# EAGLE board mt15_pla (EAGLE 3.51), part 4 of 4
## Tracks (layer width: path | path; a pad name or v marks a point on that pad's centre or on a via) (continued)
N$297  (via drill 0.61 pad 1.02)
  Top 0.305: 103.81,47.88 103.81,48.25 v104.14,48.58
  Bottom 0.305: J285. 103.82,48.26 v104.14,48.58
N$298  (via drill 0.61 pad 1.02)
  Top 0.406: 3.5,53.72 3.5,53.67 v3.17,53.34
  Bottom 0.406: J287. 3.49,53.66 v3.17,53.34
N$299  (via drill 0.61 pad 1.02)
  Top 0.406: 7.32,53.72 7.32,53.67 v6.99,53.34
  Bottom 0.406: J288. 7.3,53.66 v6.99,53.34
N$300  (via drill 0.61 pad 1.02)
  Top 0.406: 11.12,53.72 11.12,53.67 v10.79,53.34
  Bottom 0.406: J289. 11.11,53.66 v10.79,53.34
N$301  (via drill 0.61 pad 1.02)
  Top 0.305: 110.11,53.34 109.16,54.29 107.63,54.29 | 73.34,54.29 77.15,54.29 | 77.15,54.29 80.96,54.29 | 80.96,54.29 84.77,54.29 | 84.77,54.29 88.58,54.29 | 88.58,54.29 92.39,54.29 | 92.39,54.29 96.2,54.29 | 96.2,54.29 100.01,54.29 | 100.01,54.29 103.82,54.29 | 103.82,54.29 107.63,54.29 | v70.17,54.29 73.34,54.29 | 107.67,53.09 107.63,53.09 107.63,54.29 | 103.86,53.09 103.82,53.09 103.82,54.29 | 96.24,53.09 96.2,53.09 96.2,54.29 | 100.05,53.09 100.01,53.09 100.01,54.29 | 73.38,53.09 73.34,53.09 73.34,54.29 | 77.19,53.09 77.15,53.09 77.15,54.29 | 81,53.09 80.96,53.09 80.96,54.29 | 84.81,53.09 84.77,53.09 84.77,54.29 | 88.62,53.09 88.58,53.09 88.58,54.29 | 92.43,53.09 92.39,53.09 92.39,54.29
  Bottom 0.305: 5.21,53.66 5.08,53.66 5.08,52.07 8.89,52.07 | 8.89,52.07 12.7,52.07 | 12.7,52.07 16.51,52.07 | 16.51,52.07 20.32,52.07 | 20.32,52.07 24.13,52.07 | 24.13,52.07 27.94,52.07 | 27.94,52.07 31.75,52.07 | 31.75,52.07 35.56,52.07 | 35.56,52.07 39.37,52.07 | 39.37,52.07 43.18,52.07 | 43.18,52.07 46.99,52.07 | 46.99,52.07 50.8,52.07 | 50.8,52.07 54.61,52.07 | 54.61,52.07 58.42,52.07 | 58.42,52.07 62.23,52.07 | 62.36,53.66 62.23,53.66 62.23,52.07 | 58.55,53.66 58.42,53.66 58.42,52.07 | 54.74,53.66 54.61,53.66 54.61,52.07 | 50.93,53.66 50.8,53.66 50.8,52.07 | 47.12,53.66 46.99,53.66 46.99,52.07 | 39.5,53.66 39.37,53.66 39.37,52.07 | 43.31,53.66 43.18,53.66 43.18,52.07 | 24.26,53.66 24.13,53.66 24.13,52.07 | 20.45,53.66 20.32,53.66 20.32,52.07 | 28.07,53.66 27.94,53.66 27.94,52.07 | 31.88,53.66 31.75,53.66 31.75,52.07 | 35.69,53.66 35.56,53.66 35.56,52.07 | 9.02,53.66 8.89,53.66 8.89,52.07 | 12.83,53.66 12.7,53.66 12.7,52.07 | 16.64,53.66 16.51,53.66 16.51,52.07 | 62.23,52.07 67.94,52.07 v70.17,54.29
N$302  (via drill 0.61 pad 1.02)
  Top 0.406: 60.66,53.72 60.66,53.67 v60.33,53.34
  Bottom 0.406: J302. 60.64,53.66 v60.33,53.34
N$303  (via drill 0.61 pad 1.02)
  Top 0.406: 56.84,53.72 56.84,53.67 v56.52,53.34
  Bottom 0.406: J301. 56.83,53.66 v56.52,53.34
N$304  (via drill 0.61 pad 1.02)
  Top 0.406: 53.03,53.72 53.03,53.67 v52.7,53.34
  Bottom 0.406: J300. 53.02,53.66 v52.7,53.34
N$305  (via drill 0.61 pad 1.02)
  Top 0.406: 49.23,53.72 49.23,53.67 v48.9,53.34
  Bottom 0.406: J299. 49.21,53.66 v48.9,53.34
N$306  (via drill 0.61 pad 1.02)
  Top 0.406: 45.41,53.72 45.41,53.67 v45.09,53.34
  Bottom 0.406: J298. 45.4,53.66 v45.09,53.34
N$307  (via drill 0.61 pad 1.02)
  Top 0.406: 22.55,53.72 22.55,53.67 v22.23,53.34
  Bottom 0.406: J292. 22.54,53.66 v22.23,53.34
N$308  (via drill 0.61 pad 1.02)
  Top 0.406: 18.75,53.72 18.75,53.67 v18.41,53.34
  Bottom 0.406: J291. 18.73,53.66 v18.41,53.34
N$309  (via drill 0.61 pad 1.02)
  Top 0.406: 14.94,53.72 14.94,53.67 v14.61,53.34
  Bottom 0.406: J290. 14.92,53.66 v14.61,53.34
N$310  (via drill 0.61 pad 1.02)
  Top 0.406: 26.36,53.72 26.36,53.67 v26.04,53.34
  Bottom 0.406: J293. 26.35,53.66 v26.04,53.34
N$311  (via drill 0.61 pad 1.02)
  Top 0.406: 30.18,53.72 30.18,53.67 v29.84,53.34
  Bottom 0.406: J294. 30.16,53.66 v29.84,53.34
N$312  (via drill 0.61 pad 1.02)
  Top 0.406: 33.98,53.72 33.98,53.67 v33.66,53.34
  Bottom 0.406: J295. 33.97,53.66 v33.66,53.34
N$313  (via drill 0.61 pad 1.02)
  Top 0.406: 37.8,53.72 37.8,53.67 v37.47,53.34
  Bottom 0.406: J296. 37.78,53.66 v37.47,53.34
N$314  (via drill 0.61 pad 1.02)
  Top 0.406: 41.6,53.72 41.6,53.67 v41.27,53.34
  Bottom 0.406: J297. 41.59,53.66 v41.27,53.34
N$315  (via drill 0.61 pad 1.02)
  Top 0.305: 105.74,53.09 105.74,52.72 v105.41,52.39
  Bottom 0.305: J312. 105.73,52.7 v105.41,52.39
N$316  (via drill 0.61 pad 1.02)
  Top 0.305: 71.45,53.09 71.45,52.72 v71.12,52.39
  Bottom 0.305: J303. 71.44,52.7 v71.12,52.39
N$317  (via drill 0.61 pad 1.02)
  Top 0.305: 75.26,53.09 75.26,52.72 v74.93,52.39
  Bottom 0.305: J304. 75.25,52.7 v74.93,52.39
N$318  (via drill 0.61 pad 1.02)
  Top 0.305: 79.07,53.09 79.07,52.72 v78.74,52.39
  Bottom 0.305: J305. 79.06,52.7 v78.74,52.39
N$319  (via drill 0.61 pad 1.02)
  Top 0.305: 82.88,53.09 82.88,52.72 v82.55,52.39
  Bottom 0.305: J306. 82.87,52.7 v82.55,52.39
N$320  (via drill 0.61 pad 1.02)
  Top 0.305: 86.69,53.09 86.69,52.72 v86.36,52.39
  Bottom 0.305: J307. 86.68,52.7 v86.36,52.39
N$321  (via drill 0.61 pad 1.02)
  Top 0.305: 90.5,53.09 90.5,52.72 v90.17,52.39
  Bottom 0.305: J308. 90.49,52.7 v90.17,52.39
N$322  (via drill 0.61 pad 1.02)
  Top 0.305: 94.31,53.09 94.31,52.72 v93.98,52.39
  Bottom 0.305: J309. 94.3,52.7 v93.98,52.39
N$323  (via drill 0.61 pad 1.02)
  Top 0.305: 98.12,53.09 98.12,52.72 v97.79,52.39
  Bottom 0.305: J310. 98.11,52.7 v97.79,52.39
N$324  (via drill 0.61 pad 1.02)
  Top 0.305: 101.93,53.09 101.93,52.72 v101.6,52.39
  Bottom 0.305: J311. 101.92,52.7 v101.6,52.39
N$325  (via drill 0.61 pad 1.02)
  Top 0.406: 7.92,56.13 7.92,56.19 v8.26,56.52
  Bottom 0.406: J313. 7.94,56.2 v8.26,56.52
N$326  (via drill 0.61 pad 1.02)
  Top 0.406: 11.73,56.13 11.73,56.19 v12.06,56.52
  Bottom 0.406: J314. 11.75,56.2 v12.06,56.52
N$327  (via drill 0.61 pad 1.02)
  Top 0.406: 15.54,56.13 15.54,56.19 v15.88,56.52
  Bottom 0.406: J315. 15.56,56.2 v15.88,56.52
N$328  (via drill 0.61 pad 1.02)
  Top 0.305: 110.11,55.88 109.16,54.93 105.73,54.93 | 71.44,54.93 71.12,54.93 v70.17,55.88 | 71.44,54.93 75.25,54.93 | 75.25,54.93 79.06,54.93 | 79.06,54.93 82.87,54.93 | 82.87,54.93 86.68,54.93 | 86.68,54.93 90.49,54.93 | 90.49,54.93 94.3,54.93 | 94.3,54.93 98.11,54.93 | 98.11,54.93 101.92,54.93 | 101.92,54.93 105.73,54.93 | 98.07,56.13 98.11,56.13 98.11,54.93 | 101.88,56.13 101.92,56.13 101.92,54.93 | 105.69,56.13 105.73,56.13 105.73,54.93 | 82.83,56.13 82.87,56.13 82.87,54.93 | 86.64,56.13 86.68,56.13 86.68,54.93 | 90.45,56.13 90.49,56.13 90.49,54.93 | 94.26,56.13 94.3,56.13 94.3,54.93 | 71.4,56.13 71.44,56.13 71.44,54.93 | 75.21,56.13 75.25,56.13 75.25,54.93 | 79.02,56.13 79.06,56.13 79.06,54.93
  Bottom 0.305: 6.22,56.2 6.35,56.2 6.35,57.78 10.16,57.78 | 10.16,57.78 13.97,57.78 | 13.97,57.78 17.78,57.78 | 17.78,57.78 21.59,57.78 | 21.59,57.78 25.4,57.78 | 25.4,57.78 29.21,57.78 | 29.21,57.78 33.02,57.78 | 33.02,57.78 36.83,57.78 | 36.83,57.78 40.64,57.78 | 40.64,57.78 44.45,57.78 | 44.45,57.78 48.26,57.78 | 48.26,57.78 52.07,57.78 | 52.07,57.78 55.88,57.78 | 55.88,57.78 59.69,57.78 | 59.69,57.78 63.5,57.78 | 40.51,56.2 40.64,56.2 40.64,57.78 | 44.32,56.2 44.45,56.2 44.45,57.78 | 48.13,56.2 48.26,56.2 48.26,57.78 | 51.94,56.2 52.07,56.2 52.07,57.78 | 55.75,56.2 55.88,56.2 55.88,57.78 | 59.56,56.2 59.69,56.2 59.69,57.78 | 63.37,56.2 63.5,56.2 63.5,57.78 | 36.7,56.2 36.83,56.2 36.83,57.78 | 32.89,56.2 33.02,56.2 33.02,57.78 | 29.08,56.2 29.21,56.2 29.21,57.78 | 25.27,56.2 25.4,56.2 25.4,57.78 | 21.46,56.2 21.59,56.2 21.59,57.78 | 13.84,56.2 13.97,56.2 13.97,57.78 | 17.65,56.2 17.78,56.2 17.78,57.78 | 10.03,56.2 10.16,56.2 10.16,57.78 | 63.5,57.78 68.26,57.78 v70.17,55.88
N$329  (via drill 0.61 pad 1.02)
  Top 0.406: 65.08,56.13 65.08,56.19 v65.41,56.52
  Bottom 0.406: J328. 65.09,56.2 v65.41,56.52
N$330  (via drill 0.61 pad 1.02)
  Top 0.406: 61.27,56.13 61.27,56.19 v61.59,56.52
  Bottom 0.406: J327. 61.28,56.2 v61.59,56.52
N$331  (via drill 0.61 pad 1.02)
  Top 0.406: 57.45,56.13 57.45,56.19 v57.78,56.52
  Bottom 0.406: J326. 57.47,56.2 v57.78,56.52
N$332  (via drill 0.61 pad 1.02)
  Top 0.406: 53.65,56.13 53.65,56.19 v53.98,56.52
  Bottom 0.406: J325. 53.66,56.2 v53.98,56.52
N$333  (via drill 0.61 pad 1.02)
  Top 0.406: 49.84,56.13 49.84,56.19 v50.16,56.52
  Bottom 0.406: J324. 49.85,56.2 v50.16,56.52
N$334  (via drill 0.61 pad 1.02)
  Top 0.406: 26.98,56.13 26.98,56.19 v27.3,56.52
  Bottom 0.406: J318. 26.99,56.2 v27.3,56.52
N$335  (via drill 0.61 pad 1.02)
  Top 0.406: 23.16,56.13 23.16,56.19 v23.5,56.52
  Bottom 0.406: J317. 23.18,56.2 v23.5,56.52
N$336  (via drill 0.61 pad 1.02)
  Top 0.406: 19.36,56.13 19.36,56.19 v19.68,56.52
  Bottom 0.406: J316. 19.37,56.2 v19.68,56.52
N$337  (via drill 0.61 pad 1.02)
  Top 0.406: 30.79,56.13 30.79,56.19 v31.11,56.52
  Bottom 0.406: J319. 30.8,56.2 v31.11,56.52
N$338  (via drill 0.61 pad 1.02)
  Top 0.406: 34.59,56.13 34.59,56.19 v34.92,56.52
  Bottom 0.406: J320. 34.61,56.2 v34.92,56.52
N$339  (via drill 0.61 pad 1.02)
  Top 0.406: 38.41,56.13 38.41,56.19 v38.73,56.52
  Bottom 0.406: J321. 38.42,56.2 v38.73,56.52
N$340  (via drill 0.61 pad 1.02)
  Top 0.406: 42.22,56.13 42.22,56.19 v42.55,56.52
  Bottom 0.406: J322. 42.23,56.2 v42.55,56.52
N$341  (via drill 0.61 pad 1.02)
  Top 0.406: 46.02,56.13 46.02,56.19 v46.35,56.52
  Bottom 0.406: J323. 46.04,56.2 v46.35,56.52
N$342  (via drill 0.61 pad 1.02)
  Top 0.305: 107.62,56.13 107.62,56.5 v107.95,56.83
  Bottom 0.305: J338. 107.63,56.2 107.63,56.52 v107.95,56.83
N$343  (via drill 0.61 pad 1.02)
  Top 0.305: 73.33,56.13 73.33,56.5 v73.66,56.83
  Bottom 0.305: J329. 73.34,56.52 v73.66,56.83
N$344  (via drill 0.61 pad 1.02)
  Top 0.305: 77.14,56.13 77.14,56.5 v77.47,56.83
  Bottom 0.305: J330. 77.15,56.52 v77.47,56.83
N$345  (via drill 0.61 pad 1.02)
  Top 0.305: 80.95,56.13 80.95,56.5 v81.28,56.83
  Bottom 0.305: J331. 80.96,56.52 v81.28,56.83
N$346  (via drill 0.61 pad 1.02)
  Top 0.305: 84.76,56.13 84.76,56.5 v85.09,56.83
  Bottom 0.305: J332. 84.77,56.52 v85.09,56.83
N$347  (via drill 0.61 pad 1.02)
  Top 0.305: 88.57,56.13 88.57,56.5 v88.9,56.83
  Bottom 0.305: J333. 88.58,56.52 v88.9,56.83
N$348  (via drill 0.61 pad 1.02)
  Top 0.305: 92.38,56.13 92.38,56.5 v92.71,56.83
  Bottom 0.305: J334. 92.39,56.52 v92.71,56.83
N$349  (via drill 0.61 pad 1.02)
  Top 0.305: 96.19,56.13 96.19,56.5 v96.52,56.83
  Bottom 0.305: J335. 96.2,56.52 v96.52,56.83
N$350  (via drill 0.61 pad 1.02)
  Top 0.305: 100,56.13 100,56.5 v100.33,56.83
  Bottom 0.305: J336. 100.01,56.52 v100.33,56.83
N$351  (via drill 0.61 pad 1.02)
  Top 0.305: 103.81,56.13 103.81,56.5 v104.14,56.83
  Bottom 0.305: J337. 103.82,56.52 v104.14,56.83
N$352  (via drill 0.61 pad 1.02)
  Top 0.406: 3.5,61.98 3.5,61.92 v3.17,61.59
  Bottom 0.406: J339. 3.49,61.91 v3.17,61.59
N$353  (via drill 0.61 pad 1.02)
  Top 0.406: 7.32,61.98 7.32,61.92 v6.99,61.59
  Bottom 0.406: J340. 7.3,61.91 v6.99,61.59
N$354  (via drill 0.61 pad 1.02)
  Top 0.406: 11.12,61.98 11.12,61.92 v10.79,61.59
  Bottom 0.406: J341. 11.11,61.91 v10.79,61.59
N$355  (via drill 0.61 pad 1.02)
  Top 0.305: 110.11,61.59 109.16,62.55 107.63,62.55 | 73.34,62.55 77.15,62.55 | 77.15,62.55 80.96,62.55 | 80.96,62.55 84.77,62.55 | 84.77,62.55 88.58,62.55 | 88.58,62.55 92.39,62.55 | 92.39,62.55 96.2,62.55 | 96.2,62.55 100.01,62.55 | 100.01,62.55 103.82,62.55 | 103.82,62.55 107.63,62.55 | v70.17,62.55 73.34,62.55 | 107.67,61.34 107.63,61.34 107.63,62.55 | 103.86,61.34 103.82,61.34 103.82,62.55 | 100.05,61.34 100.01,61.34 100.01,62.55 | 96.24,61.34 96.2,61.34 96.2,62.55 | 92.43,61.34 92.39,61.34 92.39,62.55 | 88.62,61.34 88.58,61.34 88.58,62.55 | 84.81,61.34 84.77,61.34 84.77,62.55 | 73.38,61.34 73.34,61.34 73.34,62.55 | 77.19,61.34 77.15,61.34 77.15,62.55 | 81,61.34 80.96,61.34 80.96,62.55
  Bottom 0.305: 5.21,61.91 5.08,61.91 5.08,60.33 8.89,60.33 | 8.89,60.33 12.7,60.33 | 12.7,60.33 16.51,60.33 | 16.51,60.33 20.32,60.33 | 20.32,60.33 24.13,60.33 | 24.13,60.33 27.94,60.33 | 27.94,60.33 31.75,60.33 | 31.75,60.33 35.56,60.33 | 35.56,60.33 39.37,60.33 | 39.37,60.33 43.18,60.33 | 43.18,60.33 46.99,60.33 | 46.99,60.33 50.8,60.33 | 50.8,60.33 54.61,60.33 | 54.61,60.33 58.42,60.33 | 58.42,60.33 62.23,60.33 | 39.5,61.91 39.37,61.91 39.37,60.33 | 43.31,61.91 43.18,61.91 43.18,60.33 | 47.12,61.91 46.99,61.91 46.99,60.33 | 50.93,61.91 50.8,61.91 50.8,60.33 | 54.74,61.91 54.61,61.91 54.61,60.33 | 58.55,61.91 58.42,61.91 58.42,60.33 | 62.36,61.91 62.23,61.91 62.23,60.33 | 9.02,61.91 8.89,61.91 8.89,60.33 | 12.83,61.91 12.7,61.91 12.7,60.33 | 16.64,61.91 16.51,61.91 16.51,60.33 | 20.45,61.91 20.32,61.91 20.32,60.33 | 24.26,61.91 24.13,61.91 24.13,60.33 | 28.07,61.91 27.94,61.91 27.94,60.33 | 35.69,61.91 35.56,61.91 35.56,60.33 | 31.88,61.91 31.75,61.91 31.75,60.33 | 62.23,60.33 67.94,60.33 v70.17,62.55
N$356  (via drill 0.61 pad 1.02)
  Top 0.406: 60.66,61.98 60.66,61.92 v60.33,61.59
  Bottom 0.406: J354. 60.64,61.91 v60.33,61.59
N$357  (via drill 0.61 pad 1.02)
  Top 0.406: 56.84,61.98 56.84,61.92 v56.52,61.59
  Bottom 0.406: J353. 56.83,61.91 v56.52,61.59
N$358  (via drill 0.61 pad 1.02)
  Top 0.406: 53.03,61.98 53.03,61.92 v52.7,61.59
  Bottom 0.406: J352. 53.02,61.91 v52.7,61.59
N$359  (via drill 0.61 pad 1.02)
  Top 0.406: 49.23,61.98 49.23,61.92 v48.9,61.59
  Bottom 0.406: J351. 49.21,61.91 v48.9,61.59
N$360  (via drill 0.61 pad 1.02)
  Top 0.406: 45.41,61.98 45.41,61.92 v45.09,61.59
  Bottom 0.406: J350. 45.4,61.91 v45.09,61.59
N$361  (via drill 0.61 pad 1.02)
  Top 0.406: 22.55,61.98 22.55,61.92 v22.23,61.59
  Bottom 0.406: J344. 22.54,61.91 v22.23,61.59
N$362  (via drill 0.61 pad 1.02)
  Top 0.406: 18.75,61.98 18.75,61.92 v18.41,61.59
  Bottom 0.406: J343. 18.73,61.91 v18.41,61.59
N$363  (via drill 0.61 pad 1.02)
  Top 0.406: 14.94,61.98 14.94,61.92 v14.61,61.59
  Bottom 0.406: J342. 14.92,61.91 v14.61,61.59
N$364  (via drill 0.61 pad 1.02)
  Top 0.406: 26.36,61.98 26.36,61.92 v26.04,61.59
  Bottom 0.406: J345. 26.35,61.91 v26.04,61.59
N$365  (via drill 0.61 pad 1.02)
  Top 0.406: 30.18,61.98 30.18,61.92 v29.84,61.59
  Bottom 0.406: J346. 30.16,61.91 v29.84,61.59
N$366  (via drill 0.61 pad 1.02)
  Top 0.406: 33.98,61.98 33.98,61.92 v33.66,61.59
  Bottom 0.406: J347. 33.97,61.91 v33.66,61.59
N$367  (via drill 0.61 pad 1.02)
  Top 0.406: 37.8,61.98 37.8,61.92 v37.47,61.59
  Bottom 0.406: J348. 37.78,61.91 v37.47,61.59
N$368  (via drill 0.61 pad 1.02)
  Top 0.406: 41.6,61.98 41.6,61.92 v41.27,61.59
  Bottom 0.406: J349. 41.59,61.91 v41.27,61.59
N$369  (via drill 0.61 pad 1.02)
  Top 0.305: 105.74,61.34 105.74,60.97 v105.41,60.64
  Bottom 0.305: J364. 105.73,60.96 v105.41,60.64
N$370  (via drill 0.61 pad 1.02)
  Top 0.305: 71.45,61.34 71.45,60.97 v71.12,60.64
  Bottom 0.305: J355. 71.44,60.96 v71.12,60.64
N$371  (via drill 0.61 pad 1.02)
  Top 0.305: 75.26,61.34 75.26,60.97 v74.93,60.64
  Bottom 0.305: J356. 75.25,60.96 v74.93,60.64
N$372  (via drill 0.61 pad 1.02)
  Top 0.305: 79.07,61.34 79.07,60.97 v78.74,60.64
  Bottom 0.305: J357. 79.06,60.96 v78.74,60.64
N$373  (via drill 0.61 pad 1.02)
  Top 0.305: 82.88,61.34 82.88,60.97 v82.55,60.64
  Bottom 0.305: J358. 82.87,60.96 v82.55,60.64
N$374  (via drill 0.61 pad 1.02)
  Top 0.305: 86.69,61.34 86.69,60.97 v86.36,60.64
  Bottom 0.305: J359. 86.68,60.96 v86.36,60.64
N$375  (via drill 0.61 pad 1.02)
  Top 0.305: 90.5,61.34 90.5,60.97 v90.17,60.64
  Bottom 0.305: J360. 90.49,60.96 v90.17,60.64
N$376  (via drill 0.61 pad 1.02)
  Top 0.305: 94.31,61.34 94.31,60.97 v93.98,60.64
  Bottom 0.305: J361. 94.3,60.96 v93.98,60.64
N$377  (via drill 0.61 pad 1.02)
  Top 0.305: 98.12,61.34 98.12,60.97 v97.79,60.64
  Bottom 0.305: J362. 98.11,60.96 v97.79,60.64
N$378  (via drill 0.61 pad 1.02)
  Top 0.305: 101.93,61.34 101.93,60.97 v101.6,60.64
  Bottom 0.305: J363. 101.92,60.96 v101.6,60.64
N$379  (via drill 0.61 pad 1.02)
  Top 0.406: 7.92,64.39 7.92,64.44 v8.26,64.77
  Bottom 0.406: J365. 7.94,64.45 v8.26,64.77
N$380  (via drill 0.61 pad 1.02)
  Top 0.406: 11.73,64.39 11.73,64.44 v12.06,64.77
  Bottom 0.406: J366. 11.75,64.45 v12.06,64.77
N$381  (via drill 0.61 pad 1.02)
  Top 0.406: 15.54,64.39 15.54,64.44 v15.88,64.77
  Bottom 0.406: J367. 15.56,64.45 v15.88,64.77
N$382  (via drill 0.61 pad 1.02)
  Top 0.305: 110.11,64.14 109.16,63.18 105.73,63.18 | 71.44,63.18 71.12,63.18 v70.17,64.14 | 71.44,63.18 75.25,63.18 | 75.25,63.18 79.06,63.18 | 79.06,63.18 82.87,63.18 | 82.87,63.18 86.68,63.18 | 86.68,63.18 90.49,63.18 | 90.49,63.18 94.3,63.18 | 94.3,63.18 98.11,63.18 | 98.11,63.18 101.92,63.18 | 101.92,63.18 105.73,63.18 | 98.07,64.39 98.11,64.39 98.11,63.18 | 101.88,64.39 101.92,64.39 101.92,63.18 | 105.69,64.39 105.73,64.39 105.73,63.18 | 82.83,64.39 82.87,64.39 82.87,63.18 | 86.64,64.39 86.68,64.39 86.68,63.18 | 90.45,64.39 90.49,64.39 90.49,63.18 | 94.26,64.39 94.3,64.39 94.3,63.18 | 71.4,64.39 71.44,64.39 71.44,63.18 | 75.21,64.39 75.25,64.39 75.25,63.18 | 79.02,64.39 79.06,64.39 79.06,63.18
  Bottom 0.305: 6.22,64.45 6.35,64.45 6.35,66.04 10.16,66.04 | 10.16,66.04 13.97,66.04 | 13.97,66.04 17.78,66.04 | 17.78,66.04 21.59,66.04 | 21.59,66.04 25.4,66.04 | 25.4,66.04 29.21,66.04 | 29.21,66.04 33.02,66.04 | 33.02,66.04 36.83,66.04 | 36.83,66.04 40.64,66.04 | 40.64,66.04 44.45,66.04 | 44.45,66.04 48.26,66.04 | 48.26,66.04 52.07,66.04 | 52.07,66.04 55.88,66.04 | 55.88,66.04 59.69,66.04 | 59.69,66.04 63.5,66.04 | 63.37,64.45 63.5,64.45 63.5,66.04 | 59.56,64.45 59.69,64.45 59.69,66.04 | 55.75,64.45 55.88,64.45 55.88,66.04 | 51.94,64.45 52.07,64.45 52.07,66.04 | 48.13,64.45 48.26,64.45 48.26,66.04 | 44.32,64.45 44.45,64.45 44.45,66.04 | 40.51,64.45 40.64,64.45 40.64,66.04 | 29.08,64.45 29.21,64.45 29.21,66.04 | 25.27,64.45 25.4,64.45 25.4,66.04 | 21.46,64.45 21.59,64.45 21.59,66.04 | 17.65,64.45 17.78,64.45 17.78,66.04 | 13.84,64.45 13.97,64.45 13.97,66.04 | 10.03,64.45 10.16,64.45 10.16,66.04 | 32.89,64.45 33.02,64.45 33.02,66.04 | 36.7,64.45 36.83,64.45 36.83,66.04 | 63.5,66.04 68.26,66.04 v70.17,64.14
N$383  (via drill 0.61 pad 1.02)
  Top 0.406: 65.08,64.39 65.08,64.44 v65.41,64.77
  Bottom 0.406: J380. 65.09,64.45 v65.41,64.77
N$384  (via drill 0.61 pad 1.02)
  Top 0.406: 61.27,64.39 61.27,64.44 v61.59,64.77
  Bottom 0.406: J379. 61.28,64.45 v61.59,64.77
N$385  (via drill 0.61 pad 1.02)
  Top 0.406: 57.45,64.39 57.45,64.44 v57.78,64.77
  Bottom 0.406: J378. 57.47,64.45 v57.78,64.77
N$386  (via drill 0.61 pad 1.02)
  Top 0.406: 53.65,64.39 53.65,64.44 v53.98,64.77
  Bottom 0.406: J377. 53.66,64.45 v53.98,64.77
N$387  (via drill 0.61 pad 1.02)
  Top 0.406: 49.84,64.39 49.84,64.44 v50.16,64.77
  Bottom 0.406: J376. 49.85,64.45 v50.16,64.77
N$388  (via drill 0.61 pad 1.02)
  Top 0.406: 26.98,64.39 26.98,64.44 v27.3,64.77
  Bottom 0.406: J370. 26.99,64.45 v27.3,64.77
N$389  (via drill 0.61 pad 1.02)
  Top 0.406: 23.16,64.39 23.16,64.44 v23.5,64.77
  Bottom 0.406: J369. 23.18,64.45 v23.5,64.77
N$390  (via drill 0.61 pad 1.02)
  Top 0.406: 19.36,64.39 19.36,64.44 v19.68,64.77
  Bottom 0.406: J368. 19.37,64.45 v19.68,64.77
N$391  (via drill 0.61 pad 1.02)
  Top 0.406: 30.79,64.39 30.79,64.44 v31.11,64.77
  Bottom 0.406: J371. 30.8,64.45 v31.11,64.77
N$392  (via drill 0.61 pad 1.02)
  Top 0.406: 34.59,64.39 34.59,64.44 v34.92,64.77
  Bottom 0.406: J372. 34.61,64.45 v34.92,64.77
N$393  (via drill 0.61 pad 1.02)
  Top 0.406: 38.41,64.39 38.41,64.44 v38.73,64.77
  Bottom 0.406: J373. 38.42,64.45 v38.73,64.77
N$394  (via drill 0.61 pad 1.02)
  Top 0.406: 42.22,64.39 42.22,64.44 v42.55,64.77
  Bottom 0.406: J374. 42.23,64.45 v42.55,64.77
N$395  (via drill 0.61 pad 1.02)
  Top 0.406: 46.02,64.39 46.02,64.44 v46.35,64.77
  Bottom 0.406: J375. 46.04,64.45 v46.35,64.77
N$396  (via drill 0.61 pad 1.02)
  Top 0.305: 107.62,64.39 107.62,64.76 v107.95,65.09
  Bottom 0.305: J390. 107.63,64.77 v107.95,65.09
N$397  (via drill 0.61 pad 1.02)
  Top 0.305: 73.33,64.39 73.33,64.76 v73.66,65.09
  Bottom 0.305: J381. 73.34,64.77 v73.66,65.09
N$398  (via drill 0.61 pad 1.02)
  Top 0.305: 77.14,64.39 77.14,64.76 v77.47,65.09
  Bottom 0.305: J382. 77.15,64.77 v77.47,65.09
N$399  (via drill 0.61 pad 1.02)
  Top 0.305: 80.95,64.39 80.95,64.76 v81.28,65.09
  Bottom 0.305: J383. 80.96,64.77 v81.28,65.09
N$400  (via drill 0.61 pad 1.02)
  Top 0.305: 84.76,64.39 84.76,64.76 v85.09,65.09
  Bottom 0.305: J384. 84.77,64.77 v85.09,65.09
N$401  (via drill 0.61 pad 1.02)
  Top 0.305: 88.57,64.39 88.57,64.76 v88.9,65.09
  Bottom 0.305: J385. 88.58,64.77 v88.9,65.09
N$402  (via drill 0.61 pad 1.02)
  Top 0.305: 92.38,64.39 92.38,64.76 v92.71,65.09
  Bottom 0.305: J386. 92.39,64.77 v92.71,65.09
N$403  (via drill 0.61 pad 1.02)
  Top 0.305: 96.19,64.39 96.19,64.76 v96.52,65.09
  Bottom 0.305: J387. 96.2,64.77 v96.52,65.09
N$404  (via drill 0.61 pad 1.02)
  Top 0.305: 100,64.39 100,64.76 v100.33,65.09
  Bottom 0.305: J388. 100.01,64.77 v100.33,65.09
N$405  (via drill 0.61 pad 1.02)
  Top 0.305: 103.81,64.39 103.81,64.76 v104.14,65.09
  Bottom 0.305: J389. 103.82,64.77 v104.14,65.09
N$406  (via drill 0.61 pad 1.02)
  Top 0.406: 3.5,70.23 3.5,70.18 v3.17,69.85
  Bottom 0.406: J391. 3.49,70.17 v3.17,69.85
N$407  (via drill 0.61 pad 1.02)
  Top 0.406: 7.32,70.23 7.32,70.18 v6.99,69.85
  Bottom 0.406: J392. 7.3,70.17 v6.99,69.85
N$408  (via drill 0.61 pad 1.02)
  Top 0.406: 11.12,70.23 11.12,70.18 v10.79,69.85
  Bottom 0.406: J393. 11.11,70.17 v10.79,69.85
N$409  (via drill 0.61 pad 1.02)
  Top 0.305: 110.11,69.85 109.16,70.8 107.63,70.8 | 73.34,70.8 77.15,70.8 | 77.15,70.8 80.96,70.8 | 80.96,70.8 84.77,70.8 | 84.77,70.8 88.58,70.8 | 88.58,70.8 92.39,70.8 | 92.39,70.8 96.2,70.8 | 96.2,70.8 100.01,70.8 | 100.01,70.8 103.82,70.8 | 103.82,70.8 107.63,70.8 | v70.17,70.8 73.34,70.8 | 73.38,69.6 73.34,69.6 73.34,70.8 | 77.19,69.6 77.15,69.6 77.15,70.8 | 81,69.6 80.96,69.6 80.96,70.8 | 84.81,69.6 84.77,69.6 84.77,70.8 | 88.62,69.6 88.58,69.6 88.58,70.8 | 92.43,69.6 92.39,69.6 92.39,70.8 | 96.24,69.6 96.2,69.6 96.2,70.8 | 100.05,69.6 100.01,69.6 100.01,70.8 | 103.86,69.6 103.82,69.6 103.82,70.8 | 107.67,69.6 107.63,69.6 107.63,70.8
  Bottom 0.305: 5.21,70.17 5.08,70.17 5.08,68.58 8.89,68.58 | 8.89,68.58 12.7,68.58 | 12.7,68.58 16.51,68.58 | 16.51,68.58 20.32,68.58 | 24.13,68.58 27.94,68.58 | 27.94,68.58 31.75,68.58 | 31.75,68.58 35.56,68.58 | 35.56,68.58 39.37,68.58 | 39.37,68.58 43.18,68.58 | 43.18,68.58 46.99,68.58 | 46.99,68.58 50.8,68.58 | 50.8,68.58 54.61,68.58 | 54.61,68.58 58.42,68.58 | 58.42,68.58 62.23,68.58 | 62.36,70.17 62.23,70.17 62.23,68.58 | 58.55,70.17 58.42,70.17 58.42,68.58 | 54.74,70.17 54.61,70.17 54.61,68.58 | 50.93,70.17 50.8,70.17 50.8,68.58 | 47.12,70.17 46.99,70.17 46.99,68.58 | 43.31,70.17 43.18,70.17 43.18,68.58 | 39.5,70.17 39.37,70.17 39.37,68.58 | 9.02,70.17 8.89,70.17 8.89,68.58 | 12.83,70.17 12.7,70.17 12.7,68.58 | 16.64,70.17 16.51,70.17 16.51,68.58 | 20.45,70.17 20.32,70.17 20.32,68.58 | 20.32,68.58 24.13,68.58 | 24.26,70.17 24.13,70.17 24.13,68.58 | 28.07,70.17 27.94,70.17 27.94,68.58 | 31.88,70.17 31.75,70.17 31.75,68.58 | 35.69,70.17 35.56,70.17 35.56,68.58 | 62.23,68.58 67.94,68.58 v70.17,70.8
N$410  (via drill 0.61 pad 1.02)
  Top 0.406: 60.66,70.23 60.66,70.18 v60.33,69.85
  Bottom 0.406: J406. 60.64,70.17 v60.33,69.85
N$411  (via drill 0.61 pad 1.02)
  Top 0.406: 56.84,70.23 56.84,70.18 v56.52,69.85
  Bottom 0.406: J405. 56.83,70.17 v56.52,69.85
N$412  (via drill 0.61 pad 1.02)
  Top 0.406: 53.03,70.23 53.03,70.18 v52.7,69.85
  Bottom 0.406: J404. 53.02,70.17 v52.7,69.85
N$413  (via drill 0.61 pad 1.02)
  Top 0.406: 49.23,70.23 49.23,70.18 v48.9,69.85
  Bottom 0.406: J403. 49.21,70.17 v48.9,69.85
N$414  (via drill 0.61 pad 1.02)
  Top 0.406: 45.41,70.23 45.41,70.18 v45.09,69.85
  Bottom 0.406: J402. 45.4,70.17 v45.09,69.85
N$415  (via drill 0.61 pad 1.02)
  Top 0.406: 22.55,70.23 22.55,70.18 v22.23,69.85
  Bottom 0.406: J396. 22.54,70.17 v22.23,69.85
N$416  (via drill 0.61 pad 1.02)
  Top 0.406: 18.75,70.23 18.75,70.18 v18.41,69.85
  Bottom 0.406: J395. 18.73,70.17 v18.41,69.85
N$417  (via drill 0.61 pad 1.02)
  Top 0.406: 14.94,70.23 14.94,70.18 v14.61,69.85
  Bottom 0.406: J394. 14.92,70.17 v14.61,69.85
N$418  (via drill 0.61 pad 1.02)
  Top 0.406: 26.36,70.23 26.36,70.18 v26.04,69.85
  Bottom 0.406: J397. 26.35,70.17 v26.04,69.85
N$419  (via drill 0.61 pad 1.02)
  Top 0.406: 30.18,70.23 30.18,70.18 v29.84,69.85
  Bottom 0.406: J398. 30.16,70.17 v29.84,69.85
N$420  (via drill 0.61 pad 1.02)
  Top 0.406: 33.98,70.23 33.98,70.18 v33.66,69.85
  Bottom 0.406: J399. 33.97,70.17 v33.66,69.85
N$421  (via drill 0.61 pad 1.02)
  Top 0.406: 37.8,70.23 37.8,70.18 v37.47,69.85
  Bottom 0.406: J400. 37.78,70.17 v37.47,69.85
N$422  (via drill 0.61 pad 1.02)
  Top 0.406: 41.6,70.23 41.6,70.18 v41.27,69.85
  Bottom 0.406: J401. 41.59,70.17 v41.27,69.85
N$423  (via drill 0.61 pad 1.02)
  Top 0.305: 105.74,69.6 105.74,69.23 v105.41,68.9
  Bottom 0.305: J416. 105.73,69.22 v105.41,68.9
N$424  (via drill 0.61 pad 1.02)
  Top 0.305: 71.45,69.6 71.45,69.23 v71.12,68.9
  Bottom 0.305: J407. 71.44,69.22 v71.12,68.9
N$425  (via drill 0.61 pad 1.02)
  Top 0.305: 75.26,69.6 75.26,69.23 v74.93,68.9
  Bottom 0.305: J408. 75.25,69.22 v74.93,68.9
N$426  (via drill 0.61 pad 1.02)
  Top 0.305: 79.07,69.6 79.07,69.23 v78.74,68.9
  Bottom 0.305: J409. 79.06,69.22 v78.74,68.9
N$427  (via drill 0.61 pad 1.02)
  Top 0.305: 82.88,69.6 82.88,69.23 v82.55,68.9
  Bottom 0.305: J410. 82.87,69.22 v82.55,68.9
N$428  (via drill 0.61 pad 1.02)
  Top 0.305: 86.69,69.6 86.69,69.23 v86.36,68.9
  Bottom 0.305: J411. 86.68,69.22 v86.36,68.9
N$429  (via drill 0.61 pad 1.02)
  Top 0.305: 90.5,69.6 90.5,69.23 v90.17,68.9
  Bottom 0.305: J412. 90.49,69.22 v90.17,68.9
N$430  (via drill 0.61 pad 1.02)
  Top 0.305: 94.31,69.6 94.31,69.23 v93.98,68.9
  Bottom 0.305: J413. 94.3,69.22 v93.98,68.9
N$431  (via drill 0.61 pad 1.02)
  Top 0.305: 98.12,69.6 98.12,69.23 v97.79,68.9
  Bottom 0.305: J414. 98.11,69.22 v97.79,68.9
N$432  (via drill 0.61 pad 1.02)
  Top 0.305: 101.93,69.6 101.93,69.23 v101.6,68.9
  Bottom 0.305: J415. 101.92,69.22 v101.6,68.9
N$435
  Top 0.305: 20.32,76.83 8.89,76.83 8.89,73.66 20.32,73.66 | 20.32,73.66 20.32,76.83 | 20.32,73.66 59.69,73.66 59.69,76.83 20.32,76.83
N$436
  Top 0.305: 73.66,73.66 73.66,76.83 106.68,76.83 106.68,73.66 73.66,73.66
N$437
  Bottom 0.305: 20.32,76.83 8.89,76.83 8.89,73.66 20.32,73.66 | 20.32,76.83 59.69,76.83 59.69,73.66 20.32,73.66 | 20.32,73.66 20.32,76.83
N$438
  Bottom 0.305: 73.66,73.66 73.66,76.83 106.68,76.83 106.68,73.66 73.66,73.66
N$453
  Bottom 1.27: 58.42,0.95 58.42,4.13
N$454
  Bottom 1.27: 60.96,0.95 60.96,4.13
N$455
  Bottom 1.27: 63.5,0.95 63.5,4.13
N$456
  Bottom 1.27: 55.88,0.95 55.88,4.13
N$458
  Bottom 1.27: 66.04,0.95 66.04,4.13
N$459
  Bottom 1.27: 68.58,0.95 68.58,3.81
N$460
  Bottom 1.27: 71.12,0.95 71.12,3.81
Q0
  Bottom 0.406: 71.75,6.99 71.63,6.99 | 71.75,6.99 71.75,8.26 73.03,9.53 73.03,11.43 | 73.03,11.43 73.15,11.43 | 73.03,11.43 73.03,12.7 71.75,13.97 71.75,15.24 | 71.75,15.24 71.63,15.24 | 71.75,15.24 71.75,16.51 73.03,17.78 73.03,19.68 | 73.03,19.68 73.15,19.68 | 73.03,19.68 73.03,20.95 71.75,22.23 71.75,23.5 | 71.75,23.5 71.63,23.5 | 71.75,23.5 71.75,24.77 73.03,26.04 73.03,27.94 | 73.03,27.94 73.15,27.94 | 73.03,27.94 73.03,29.21 71.75,30.48 71.75,31.75 | 71.75,31.75 71.63,31.75 | 71.75,31.75 71.75,33.02 73.03,34.29 73.03,36.2 | 73.03,36.2 73.15,36.2 | 73.03,36.2 73.03,37.47 71.75,38.73 71.75,40.01 | 71.75,40.01 71.63,40.01 | 71.75,40.01 71.75,41.27 73.03,42.55 73.03,44.45 | 73.03,44.45 73.15,44.45 | 73.03,44.45 73.03,45.72 71.75,46.99 71.75,48.26 | 71.75,48.26 71.63,48.26 | 71.75,48.26 71.75,49.53 73.03,50.8 73.03,52.7 | 71.75,56.52 71.75,55.24 73.03,53.98 73.03,52.7 | 71.75,56.52 71.63,56.52 | 71.75,56.52 71.75,57.78 73.03,59.05 73.03,60.96 | 73.03,60.96 73.15,60.96 | 73.03,60.96 73.03,62.23 71.75,63.5 71.75,64.77 | 71.75,64.77 71.63,64.77 | 71.75,64.77 71.75,66.04 73.03,67.31 73.03,69.22 73.15,69.22 | 73.03,52.7 73.15,52.7 | 71.75,6.99 71.75,5.71 73.66,3.81
  Bottom 1.27: 73.66,0.95 73.66,3.81 73.66,4.13
Q1
  Bottom 0.406: 75.56,6.99 75.44,6.99 | 75.56,6.99 75.56,8.26 76.83,9.53 76.83,11.43 | 75.56,15.24 75.56,13.97 76.83,12.7 76.83,11.43 | 76.83,11.43 76.96,11.43 | 76.96,69.22 76.83,69.22 76.83,67.31 75.56,66.04 75.56,64.77 | 76.83,60.96 76.83,62.23 75.56,63.5 75.56,64.77 | 75.56,64.77 75.44,64.77 | 75.56,56.52 75.56,57.78 76.83,59.05 76.83,60.96 | 76.83,60.96 76.96,60.96 | 75.56,56.52 75.44,56.52 | 75.56,56.52 75.56,55.24 76.83,53.98 76.83,52.7 | 76.83,52.7 76.96,52.7 | 75.56,48.26 75.56,49.53 76.83,50.8 76.83,52.7 | 75.56,48.26 75.44,48.26 | 75.56,48.26 75.56,46.99 76.83,45.72 76.83,44.45 | 75.56,40.01 75.56,41.27 76.83,42.55 76.83,44.45 | 76.83,44.45 76.96,44.45 | 75.56,40.01 75.44,40.01 | 75.56,40.01 75.56,38.73 76.83,37.47 76.83,36.2 | 75.56,31.75 75.56,33.02 76.83,34.29 76.83,36.2 | 76.83,36.2 76.96,36.2 | 75.56,31.75 75.44,31.75 | 75.56,31.75 75.56,30.48 76.83,29.21 76.83,27.94 | 76.83,27.94 76.96,27.94 | 75.56,23.5 75.56,24.77 76.83,26.04 76.83,27.94 | 75.56,23.5 75.44,23.5 | 75.56,23.5 75.56,22.23 76.83,20.95 76.83,19.68 | 76.83,19.68 76.96,19.68 | 75.56,15.24 75.44,15.24 | 75.56,15.24 75.56,16.51 76.83,17.78 76.83,19.68 | 75.56,6.99 75.56,5.71 76.2,5.08 76.2,4.13
  Bottom 1.27: 76.2,0.95 76.2,4.13
Q2
  Bottom 0.406: 79.38,6.99 79.25,6.99 | 79.38,6.99 79.38,8.26 80.64,9.53 80.64,11.43 | 80.64,11.43 80.77,11.43 | 80.64,11.43 80.64,12.7 79.38,13.97 79.38,15.24 | 80.77,69.22 80.64,69.22 80.64,67.31 79.38,66.04 79.38,64.77 | 79.38,56.52 79.38,57.78 80.64,59.05 80.64,60.96 | 80.64,60.96 80.77,60.96 | 80.64,60.96 80.64,62.23 79.38,63.5 79.38,64.77 | 79.38,64.77 79.25,64.77 | 79.38,56.52 79.25,56.52 | 79.38,56.52 79.38,55.24 80.64,53.98 80.64,52.7 | 80.64,52.7 80.77,52.7 | 79.38,48.26 79.38,49.53 80.64,50.8 80.64,52.7 | 80.64,44.45 80.64,45.72 79.38,46.99 79.38,48.26 | 79.38,48.26 79.25,48.26 | 80.64,44.45 80.77,44.45 | 79.38,40.01 79.38,41.27 80.64,42.55 80.64,44.45 | 80.64,36.2 80.64,37.47 79.38,38.73 79.38,40.01 | 79.38,40.01 79.25,40.01 | 79.38,31.75 79.38,33.02 80.64,34.29 80.64,36.2 | 80.64,36.2 80.77,36.2 | 80.64,27.94 80.64,29.21 79.38,30.48 79.38,31.75 | 79.38,31.75 79.25,31.75 | 79.38,23.5 79.38,24.77 80.64,26.04 80.64,27.94 | 80.64,27.94 80.77,27.94 | 79.38,23.5 79.25,23.5 | 79.38,23.5 79.38,22.23 80.64,20.95 80.64,19.68 | 80.64,19.68 80.77,19.68 | 79.38,15.24 79.25,15.24 | 79.38,15.24 79.38,16.51 80.64,17.78 80.64,19.68 | 79.38,6.99 79.38,5.71 78.74,5.08 78.74,4.13
  Bottom 1.27: 78.74,0.95 78.74,4.13
Q3
  Bottom 0.406: 83.19,6.99 83.06,6.99 | 83.19,6.99 83.19,8.26 84.45,9.53 84.45,11.43 | 83.19,15.24 83.19,13.97 84.45,12.7 84.45,11.43 | 84.45,11.43 84.58,11.43 | 84.58,69.22 84.45,69.22 84.45,67.31 83.19,66.04 83.19,64.77 | 83.19,64.77 83.06,64.77 | 83.19,64.77 83.19,63.5 84.45,62.23 84.45,60.96 | 83.19,56.52 83.19,57.78 84.45,59.05 84.45,60.96 | 83.19,56.52 83.06,56.52 | 83.19,56.52 83.19,55.24 84.45,53.98 84.45,52.7 | 84.45,52.7 84.58,52.7 | 83.19,48.26 83.19,49.53 84.45,50.8 84.45,52.7 | 83.19,48.26 83.06,48.26 | 83.19,48.26 83.19,46.99 84.45,45.72 84.45,44.45 | 84.45,44.45 84.58,44.45 | 83.19,40.01 83.19,41.27 84.45,42.55 84.45,44.45 | 83.19,40.01 83.06,40.01 | 83.19,40.01 83.19,38.73 84.45,37.47 84.45,36.2 | 84.45,36.2 84.58,36.2 | 83.19,31.75 83.19,33.02 84.45,34.29 84.45,36.2 | 83.19,31.75 83.06,31.75 | 83.19,31.75 83.19,30.48 84.45,29.21 84.45,27.94 | 84.45,27.94 84.58,27.94 | 83.19,23.5 83.19,24.77 84.45,26.04 84.45,27.94 | 83.19,23.5 83.06,23.5 | 83.19,23.5 83.19,22.23 84.45,20.95 84.45,19.68 | 84.45,19.68 84.58,19.68 | 83.19,15.24 83.06,15.24 | 83.19,15.24 83.19,16.51 84.45,17.78 84.45,19.68 | 84.45,60.96 84.58,60.96 | 81.28,4.13 81.28,4.45 83.19,6.35 83.19,6.99
  Bottom 1.27: 81.28,0.95 81.28,4.13
Q4
  Bottom 0.406: 87,6.99 86.87,6.99 | 87,6.99 87,8.26 88.27,9.53 88.27,11.43 | 88.27,11.43 88.39,11.43 | 88.27,11.43 88.27,12.7 87,13.97 87,15.24 | 87,15.24 86.87,15.24 | 87,15.24 87,16.51 88.27,17.78 88.27,19.68 | 88.27,19.68 88.27,20.95 87,22.23 87,23.5 | 88.27,19.68 88.39,19.68 | 87,23.5 86.87,23.5 | 87,23.5 87,24.77 88.27,26.04 88.27,27.94 | 87,31.75 87,33.02 88.27,34.29 88.27,36.2 | 87,31.75 86.87,31.75 | 87,31.75 87,30.48 88.27,29.21 88.27,27.94 | 88.27,27.94 88.39,27.94 | 88.27,36.2 88.39,36.2 | 88.27,36.2 88.27,37.47 87,38.73 87,40.01 | 87,40.01 86.87,40.01 | 87,40.01 87,41.27 88.27,42.55 88.27,44.45 | 88.27,52.7 88.27,53.98 87,55.24 87,56.52 | 88.27,52.7 88.39,52.7 | 87,48.26 87,49.53 88.27,50.8 88.27,52.7 | 87,48.26 86.87,48.26 | 87,48.26 87,46.99 88.27,45.72 88.27,44.45 | 88.27,44.45 88.39,44.45 | 87,56.52 87,57.78 88.27,59.05 88.27,60.96 | 87,56.52 86.87,56.52 | 88.27,60.96 88.39,60.96 | 88.27,60.96 88.27,62.23 87,63.5 87,64.77 | 87,64.77 86.87,64.77 | 87,64.77 87,66.04 88.27,67.31 88.27,69.22 88.39,69.22 | 87,6.99 87,5.71 87.31,5.4 88.27,5.4 88.9,4.76 88.9,4.13
  Bottom 1.27: 88.9,0.95 88.9,4.13
Q5
  Bottom 0.406: 90.81,15.24 90.81,13.97 92.08,12.7 92.08,11.43 | 90.81,6.99 90.68,6.99 | 90.81,6.99 90.81,8.26 92.08,9.53 92.08,11.43 | 92.08,11.43 92.2,11.43 | 90.81,15.24 90.68,15.24 | 90.81,15.24 90.81,16.51 92.08,17.78 92.08,19.68 | 90.81,23.5 90.81,24.77 92.08,26.04 92.08,27.94 | 90.81,23.5 90.68,23.5 | 90.81,23.5 90.81,22.23 92.08,20.95 92.08,19.68 | 92.08,19.68 92.2,19.68 | 92.08,27.94 92.2,27.94 | 92.08,27.94 92.08,29.21 90.81,30.48 90.81,31.75 | 90.81,31.75 90.68,31.75 | 90.81,31.75 90.81,33.02 92.08,34.29 92.08,36.2 | 90.81,40.01 90.81,41.27 92.08,42.55 92.08,44.45 | 90.81,40.01 90.68,40.01 | 90.81,40.01 90.81,38.73 92.08,37.47 92.08,36.2 | 92.08,36.2 92.2,36.2 | 92.08,52.7 92.08,53.98 90.81,55.24 90.81,56.52 | 92.08,52.7 92.2,52.7 | 90.81,48.26 90.81,49.53 92.08,50.8 92.08,52.7 | 92.08,44.45 92.2,44.45 | 92.08,44.45 92.08,45.72 90.81,46.99 90.81,48.26 | 90.81,48.26 90.68,48.26 | 90.81,56.52 90.68,56.52 | 90.81,56.52 90.81,57.78 92.08,59.05 92.08,60.96 | 90.81,64.77 90.81,66.04 92.08,67.31 92.08,69.22 92.2,69.22 | 90.81,64.77 90.68,64.77 | 90.81,64.77 90.81,63.5 92.08,62.23 92.08,60.96 | 92.08,60.96 92.2,60.96 | 90.81,6.99 90.81,6.03 91.44,5.4 91.44,4.13
  Bottom 1.27: 91.44,0.95 91.44,4.13
Q6
  Bottom 0.406: 94.61,6.99 94.49,6.99 | 94.61,6.99 94.61,8.26 95.89,9.53 95.89,11.43 | 94.61,15.24 94.61,13.97 95.89,12.7 95.89,11.43 | 94.61,15.24 94.49,15.24 | 94.61,15.24 94.61,16.51 95.89,17.78 95.89,19.68 | 95.89,11.43 96.01,11.43 | 94.61,23.5 94.61,24.77 95.89,26.04 95.89,27.94 | 94.61,23.5 94.49,23.5 | 94.61,23.5 94.61,22.23 95.89,20.95 95.89,19.68 | 95.89,19.68 96.01,19.68 | 95.89,27.94 96.01,27.94 | 95.89,27.94 95.89,29.21 94.61,30.48 94.61,31.75 | 94.61,31.75 94.61,33.02 95.89,34.29 95.89,36.2 | 94.61,31.75 94.49,31.75 | 94.61,40.01 94.61,38.73 95.89,37.47 95.89,36.2 | 94.61,40.01 94.49,40.01 | 94.61,40.01 94.61,41.27 95.89,42.55 95.89,44.45 | 95.89,36.2 96.01,36.2 | 95.89,52.7 95.89,53.98 94.61,55.24 94.61,56.52 | 95.89,52.7 96.01,52.7 | 94.61,48.26 94.61,49.53 95.89,50.8 95.89,52.7 | 94.61,48.26 94.49,48.26 | 94.61,48.26 94.61,46.99 95.89,45.72 95.89,44.45 | 95.89,44.45 96.01,44.45 | 94.61,64.77 94.61,63.5 95.89,62.23 95.89,60.96 | 94.61,64.77 94.49,64.77 | 94.61,64.77 94.61,66.04 95.89,67.31 95.89,69.22 96.01,69.22 | 95.89,60.96 96.01,60.96 | 94.61,56.52 94.61,57.78 95.89,59.05 95.89,60.96 | 94.61,56.52 94.49,56.52 | 94.61,6.99 94.61,6.03 93.98,5.4 93.98,4.13
  Bottom 1.27: 93.98,0.95 93.98,4.13
Q7
  Bottom 0.406: 98.42,6.99 98.3,6.99 | 98.42,6.99 98.42,8.26 99.69,9.53 99.69,11.43 | 99.69,11.43 99.82,11.43 | 99.69,11.43 99.69,12.7 98.42,13.97 98.42,15.24 | 98.42,15.24 98.3,15.24 | 98.42,15.24 98.42,16.51 99.69,17.78 99.69,19.68 | 99.69,19.68 99.82,19.68 | 99.69,19.68 99.69,20.95 98.42,22.23 98.42,23.5 | 98.42,23.5 98.3,23.5 | 98.42,23.5 98.42,24.77 99.69,26.04 99.69,27.94 | 99.69,27.94 99.82,27.94 | 99.69,27.94 99.69,29.21 98.42,30.48 98.42,31.75 | 98.42,31.75 98.42,33.02 99.69,34.29 99.69,36.2 | 98.42,31.75 98.3,31.75 | 98.42,40.01 98.42,38.73 99.69,37.47 99.69,36.2 | 98.42,40.01 98.3,40.01 | 98.42,40.01 98.42,41.27 99.69,42.55 99.69,44.45 | 99.69,36.2 99.82,36.2 | 99.69,44.45 99.82,44.45 | 99.69,44.45 99.69,45.72 98.42,46.99 98.42,48.26 | 98.42,48.26 98.3,48.26 | 98.42,48.26 98.42,49.53 99.69,50.8 99.69,52.7 | 99.69,52.7 99.82,52.7 | 99.69,52.7 99.69,53.98 98.42,55.24 98.42,56.52 | 98.42,64.77 98.42,66.04 99.69,67.31 99.69,69.22 99.82,69.22 | 98.42,64.77 98.3,64.77 | 98.42,64.77 98.42,63.5 99.69,62.23 99.69,60.96 | 99.69,60.96 99.82,60.96 | 98.42,56.52 98.42,57.78 99.69,59.05 99.69,60.96 | 98.42,56.52 98.3,56.52 | 98.42,6.99 98.42,6.35 96.52,4.45 96.52,4.13
  Bottom 1.27: 96.52,0.95 96.52,4.13
Q8
  Bottom 0.406: 103.5,11.43 103.63,11.43 | 103.5,11.43 103.5,12.7 102.23,13.97 102.23,15.24 | 102.23,15.24 102.11,15.24 | 102.23,15.24 102.23,16.51 103.5,17.78 103.5,19.68 | 102.23,23.5 102.23,24.77 103.5,26.04 103.5,27.94 | 102.23,23.5 102.11,23.5 | 102.23,23.5 102.23,22.23 103.5,20.95 103.5,19.68 | 103.5,19.68 103.63,19.68 | 103.5,27.94 103.63,27.94 | 103.5,27.94 103.5,29.21 102.23,30.48 102.23,31.75 | 102.23,31.75 102.11,31.75 | 102.23,31.75 102.23,33.02 103.5,34.29 103.5,36.2 | 103.5,36.2 103.63,36.2 | 103.5,36.2 103.5,37.47 102.23,38.73 102.23,40.01 | 102.23,40.01 102.11,40.01 | 102.23,40.01 102.23,41.27 103.5,42.55 103.5,44.45 | 103.5,52.7 103.5,53.98 102.23,55.24 102.23,56.52 | 103.5,52.7 103.63,52.7 | 102.23,48.26 102.23,49.53 103.5,50.8 103.5,52.7 | 102.23,48.26 102.11,48.26 | 102.23,48.26 102.23,46.99 103.5,45.72 103.5,44.45 | 103.5,44.45 103.63,44.45 | 102.23,64.77 102.23,66.04 103.5,67.31 103.5,69.22 103.63,69.22 | 102.23,56.52 102.11,56.52 | 102.23,56.52 102.23,57.78 103.5,59.05 103.5,60.96 | 103.5,60.96 103.63,60.96 | 103.5,60.96 103.5,62.23 102.23,63.5 102.23,64.77 | 102.23,64.77 102.11,64.77 | 103.5,11.43 103.5,9.53 102.23,8.26 102.23,6.99 102.11,6.99 102.11,5.91 101.6,5.4 101.6,4.13
  Bottom 1.27: 101.6,0.95 101.6,4.13
Q9
  Bottom 0.406: 107.31,11.43 107.44,11.43 | 107.31,11.43 107.31,12.7 106.05,13.97 106.05,15.24 | 106.05,15.24 105.92,15.24 | 106.05,15.24 106.05,16.51 107.31,17.78 107.31,19.68 | 107.31,19.68 107.44,19.68 | 107.31,19.68 107.31,20.95 106.05,22.23 106.05,23.5 | 106.05,23.5 105.92,23.5 | 106.05,23.5 106.05,24.77 107.31,26.04 107.31,27.94 | 107.31,27.94 107.44,27.94 | 107.31,27.94 107.31,29.21 106.05,30.48 106.05,31.75 | 106.05,31.75 105.92,31.75 | 106.05,31.75 106.05,33.02 107.31,34.29 107.31,36.2 | 106.05,40.01 106.05,38.73 107.31,37.47 107.31,36.2 | 106.05,40.01 105.92,40.01 | 106.05,40.01 106.05,41.27 107.31,42.55 107.31,44.45 | 107.31,36.2 107.44,36.2 | 107.31,44.45 107.44,44.45 | 107.31,44.45 107.31,45.72 106.05,46.99 106.05,48.26 | 106.05,48.26 105.92,48.26 | 106.05,48.26 106.05,49.53 107.31,50.8 107.31,52.7 | 107.31,52.7 107.44,52.7 | 107.31,52.7 107.31,53.98 106.05,55.24 106.05,56.52 | 106.05,56.52 105.92,56.52 | 106.05,56.52 106.05,57.78 107.31,59.05 107.31,60.96 | 107.31,60.96 107.44,60.96 | 107.31,60.96 107.31,62.23 106.05,63.5 106.05,64.77 | 106.05,64.77 105.92,64.77 | 106.05,64.77 106.05,66.04 107.31,67.31 107.31,69.22 107.44,69.22 | 107.31,11.43 107.31,9.53 106.05,8.26 106.05,6.99 105.92,6.99 105.92,6.54 104.14,4.76 104.14,4.13
  Bottom 1.27: 104.14,0.95 104.14,4.13
S$1
  Top 2: 20,-1 -1,-1 -1,20
S$2
  Top 2: 95.87,-1 116.87,-1 116.87,20
S$3
  Top 2: 20,79.73 -1,79.73 -1,58.73
S$4
  Top 2: 116.87,58.73 116.87,79.73 95.87,79.73
S$5
  Bottom 2: 20,-1 -1,-1 -1,20
S$6
  Bottom 2: 95.87,-1 116.87,-1 116.87,20
S$7
  Bottom 2: 20,79.73 -1,79.73 -1,58.73
S$8
  Bottom 2: 116.87,58.73 116.87,79.73 95.87,79.73
VCC  (via drill 0.61 pad 1.02)
  Top 0.406: T17. 72.39,8.64 72.39,9.21 72.39,9.78 T28. | T18. 76.2,8.64 76.2,9.21 76.2,9.78 T44. | T19. 80.01,8.64 80.01,9.21 80.01,9.78 T45. | T20. 83.82,8.64 83.82,9.21 83.82,9.78 T46. | T21. 87.63,8.64 87.63,9.21 87.63,9.78 T47. | T22. 91.44,8.64 91.44,9.21 91.44,9.78 T48. | T23. 95.25,8.64 95.25,9.21 95.25,9.78 T49. | T24. 99.06,8.64 99.06,9.21 99.06,9.78 T50. | T25. 102.87,8.64 102.87,9.21 102.87,9.78 T51. | T26. 106.68,8.64 106.68,9.21 106.68,9.78 T52. | T78. 106.68,16.89 106.68,17.46 106.68,18.03 T104. | T77. 102.87,16.89 102.87,17.46 102.87,18.03 T103. | T76. 99.06,16.89 99.06,17.46 99.06,18.03 T102. | T75. 95.25,16.89 95.25,17.46 95.25,18.03 T101. | T74. 91.44,16.89 91.44,17.46 91.44,18.03 T100. | T73. 87.63,16.89 87.63,17.46 87.63,18.03 T99. | T72. 83.82,16.89 83.82,17.46 83.82,18.03 T98. | T71. 80.01,16.89 80.01,17.46 80.01,18.03 T97. | T54. 72.39,16.89 72.39,17.46 72.39,18.03 T80. | T70. 76.2,16.89 76.2,17.46 76.2,18.03 T96. | T106. 72.39,25.15 72.39,25.72 72.39,26.29 T132. | T122. 76.2,25.15 76.2,25.72 76.2,26.29 T148. | T123. 80.01,25.15 80.01,25.72 80.01,26.29 T149. | T124. 83.82,25.15 83.82,25.72 83.82,26.29 T150. | T125. 87.63,25.15 87.63,25.72 87.63,26.29 T151. | T126. 91.44,25.15 91.44,25.72 91.44,26.29 T152. | T127. 95.25,25.15 95.25,25.72 95.25,26.29 T153. | T128. 99.06,25.15 99.06,25.72 99.06,26.29 T154. | T129. 102.87,25.15 102.87,25.72 102.87,26.29 T155. | T130. 106.68,25.15 106.68,25.72 106.68,26.29 T156. | T182. 106.68,33.4 106.68,33.97 106.68,34.54 T208. | T178. 91.44,33.4 91.44,33.97 91.44,34.54 T204. | T177. 87.63,33.4 87.63,33.97 87.63,34.54 T203. | T176. 83.82,33.4 83.82,33.97 83.82,34.54 T202.
  Top 0.406: T175. 80.01,33.4 80.01,33.97 80.01,34.54 T201. | T174. 76.2,33.4 76.2,33.97 76.2,34.54 T200. | T158. 72.39,33.4 72.39,33.97 72.39,34.54 T184. | T210. 72.39,41.66 72.39,42.23 72.39,42.8 T236. | T226. 76.2,41.66 76.2,42.23 76.2,42.8 T252. | T227. 80.01,41.66 80.01,42.23 80.01,42.8 T253. | T228. 83.82,41.66 83.82,42.23 83.82,42.8 T254. | T229. 87.63,41.66 87.63,42.23 87.63,42.8 T255. | T230. 91.44,41.66 91.44,42.23 91.44,42.8 T256. | T231. 95.25,41.66 95.25,42.23 95.25,42.8 T257. | T232. 99.06,41.66 99.06,42.23 99.06,42.8 T258. | T233. 102.87,41.66 102.87,42.23 102.87,42.8 T259. | T234. 106.68,41.66 106.68,42.23 106.68,42.8 T260. | T286. 106.68,49.91 106.68,50.48 106.68,51.05 T312. | T285. 102.87,49.91 102.87,50.48 102.87,51.05 T311. | T284. 99.06,49.91 99.06,50.48 99.06,51.05 T310. | T283. 95.25,49.91 95.25,50.48 95.25,51.05 T309. | T282. 91.44,49.91 91.44,50.48 91.44,51.05 T308. | T281. 87.63,49.91 87.63,50.48 87.63,51.05 T307. | T280. 83.82,49.91 83.82,50.48 83.82,51.05 T306. | T279. 80.01,49.91 80.01,50.48 80.01,51.05 T305. | T262. 72.39,49.91 72.39,50.48 72.39,51.05 T288. | T278. 76.2,49.91 76.2,50.48 76.2,51.05 T304. | T314. 72.39,58.17 72.39,58.74 72.39,59.31 T340. | T330. 76.2,58.17 76.2,58.74 76.2,59.31 T356. | T331. 80.01,58.17 80.01,58.74 80.01,59.31 T357. | T332. 83.82,58.17 83.82,58.74 83.82,59.31 T358. | T333. 87.63,58.17 87.63,58.74 87.63,59.31 T359. | T334. 91.44,58.17 91.44,58.74 91.44,59.31 T360. | T335. 95.25,58.17 95.25,58.74 95.25,59.31 T361. | T338. 106.68,58.17 106.68,58.74 106.68,59.31 T364. | T337. 102.87,58.17 102.87,58.74 102.87,59.31 T363. | T336. 99.06,58.17 99.06,58.74 99.06,59.31 T362.
  Top 0.406: T366. 72.39,66.42 72.39,66.99 72.39,67.56 T392. | T382. 76.2,66.42 76.2,66.99 76.2,67.56 T408. | T383. 80.01,66.42 80.01,66.99 80.01,67.56 T409. | T384. 83.82,66.42 83.82,66.99 83.82,67.56 T410. | T385. 87.63,66.42 87.63,66.99 87.63,67.56 T411. | T386. 91.44,66.42 91.44,66.99 91.44,67.56 T412. | T388. 99.06,66.42 99.06,66.99 99.06,67.56 T414. | T387. 95.25,66.42 95.25,66.99 95.25,67.56 T413. | T389. 102.87,66.42 102.87,66.99 102.87,67.56 T415. | T390. 106.68,66.42 106.68,66.99 106.68,67.56 T416. | T205. 95.25,34.54 95.25,33.97 95.25,33.4 T179. | T180. 99.06,33.4 99.06,33.97 99.06,34.54 T206. | T181. 102.87,33.4 102.87,33.97 102.87,34.54 T207. | 114.62,69.85 R16. | 114.62,64.14 R15. | 114.62,61.59 R14. | 114.62,55.88 R13. | 114.62,53.34 R12. | 114.62,47.62 R11. | 114.62,45.09 R10. | 114.62,36.83 R8. | 114.62,39.37 R9. | 114.62,28.57 R6. | 114.62,31.11 R7. | 114.62,20.32 R4. | 114.62,22.86 R5. | 114.62,12.06 R1. | 114.62,14.61 R2. | 114.62,6.35 R3.
  Top 0.813: 67.94,14.22 67.94,12.45 68.33,12.06 68.33,12 71.12,9.21 69.53,7.62 69.53,6.99 68.52,5.97 67.94,5.97 | 67.94,22.48 67.94,20.7 68.33,20.32 68.33,20.26 71.12,17.46 | 67.94,30.73 67.94,28.96 68.33,28.57 68.33,28.51 71.12,25.72 | 67.94,38.99 67.94,37.21 68.33,36.83 68.33,36.77 71.12,33.97 | 67.94,47.24 67.94,45.47 68.33,45.09 68.33,45.02 71.12,42.23 | 67.94,55.5 67.94,53.72 68.33,53.34 68.33,53.28 71.12,50.48 | 67.94,63.75 67.94,61.98 68.33,61.59 68.33,61.53 71.12,58.74 | 68.33,69.85 68.33,69.79 71.12,66.99
  Top 1.016: v114.62,66.99 106.68,66.99 102.87,66.99 99.06,66.99 95.25,66.99 91.44,66.99 87.63,66.99 83.82,66.99 80.01,66.99 76.2,66.99 72.39,66.99 71.12,66.99 | v114.62,58.74 106.68,58.74 102.87,58.74 99.06,58.74 95.25,58.74 91.44,58.74 87.63,58.74 83.82,58.74 80.01,58.74 76.2,58.74 72.39,58.74 71.12,58.74 | v114.62,50.48 106.68,50.48 102.87,50.48 99.06,50.48 95.25,50.48 91.44,50.48 87.63,50.48 83.82,50.48 80.01,50.48 76.2,50.48 72.39,50.48 71.12,50.48 | v114.62,42.23 106.68,42.23 102.87,42.23 99.06,42.23 95.25,42.23 91.44,42.23 87.63,42.23 83.82,42.23 80.01,42.23 76.2,42.23 72.39,42.23 71.12,42.23 | v114.62,33.97 106.68,33.97 102.87,33.97 99.06,33.97 95.25,33.97 91.44,33.97 87.63,33.97 83.82,33.97 80.01,33.97 76.2,33.97 72.39,33.97 71.12,33.97 | v114.62,25.72 106.68,25.72 102.87,25.72 99.06,25.72 95.25,25.72 91.44,25.72 87.63,25.72 83.82,25.72 80.01,25.72 76.2,25.72 72.39,25.72 71.12,25.72 | v114.62,17.46 106.68,17.46 102.87,17.46 99.06,17.46 95.25,17.46 91.44,17.46 87.63,17.46 83.82,17.46 80.01,17.46 76.2,17.46 72.39,17.46 71.12,17.46 | 71.12,9.21 72.39,9.21 76.2,9.21 80.01,9.21 83.82,9.21 87.63,9.21 91.44,9.21 95.25,9.21 99.06,9.21 102.87,9.21 106.68,9.21 v114.62,9.21
  Top 1.27: 114.62,69.85 v114.62,66.99 114.62,64.14 114.62,61.59 v114.62,58.74 114.62,55.88 114.62,53.34 v114.62,50.48 114.62,47.62 114.62,45.09 v114.62,42.23 114.62,39.37 114.62,36.83 v114.62,33.97 114.62,31.11 114.62,28.57 v114.62,25.72 114.62,22.86 114.62,20.32 v114.62,17.46 114.62,14.61 114.62,12.06 v114.62,9.21 114.62,6.35 v114.62,4.76 112.39,2.54
  Top 2.54: v83.82,2.54 v86.36,2.54 v99.06,2.54 v106.68,2.54 v109.22,2.54 v111.76,2.54 112.39,2.54
  Bottom 1.27: v114.62,66.99 v114.62,58.74 v114.62,50.48 v114.62,42.23 v114.62,33.97 v114.62,25.72 v114.62,17.46 v114.62,9.21 v114.62,4.76 114.62,4.45 114.3,4.13 | 114.3,4.13 114.3,0.95 | 111.76,4.13 v111.76,2.54 111.76,0.95 | 114.3,4.13 111.76,4.13 | 109.22,4.13 v109.22,2.54 109.22,0.95 | 111.76,4.13 109.22,4.13 | 106.68,0.95 v106.68,2.54 106.68,4.13 109.22,4.13 | 99.06,0.95 v99.06,2.54 99.06,4.13 | 86.36,0.95 v86.36,2.54 86.36,4.13 | 83.82,0.95 v83.82,2.54 83.82,4.13
  pour Top (isolate 0.356): 114.94,6.35 114.94,1.27 112.39,1.27 112.39,18.41 112.39,70.48 114.94,70.48
  pour Bottom (isolate 0.356): 109.22,11.43 109.22,4.45 114.94,4.45 114.94,70.48 109.22,70.48 109.22,10.79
